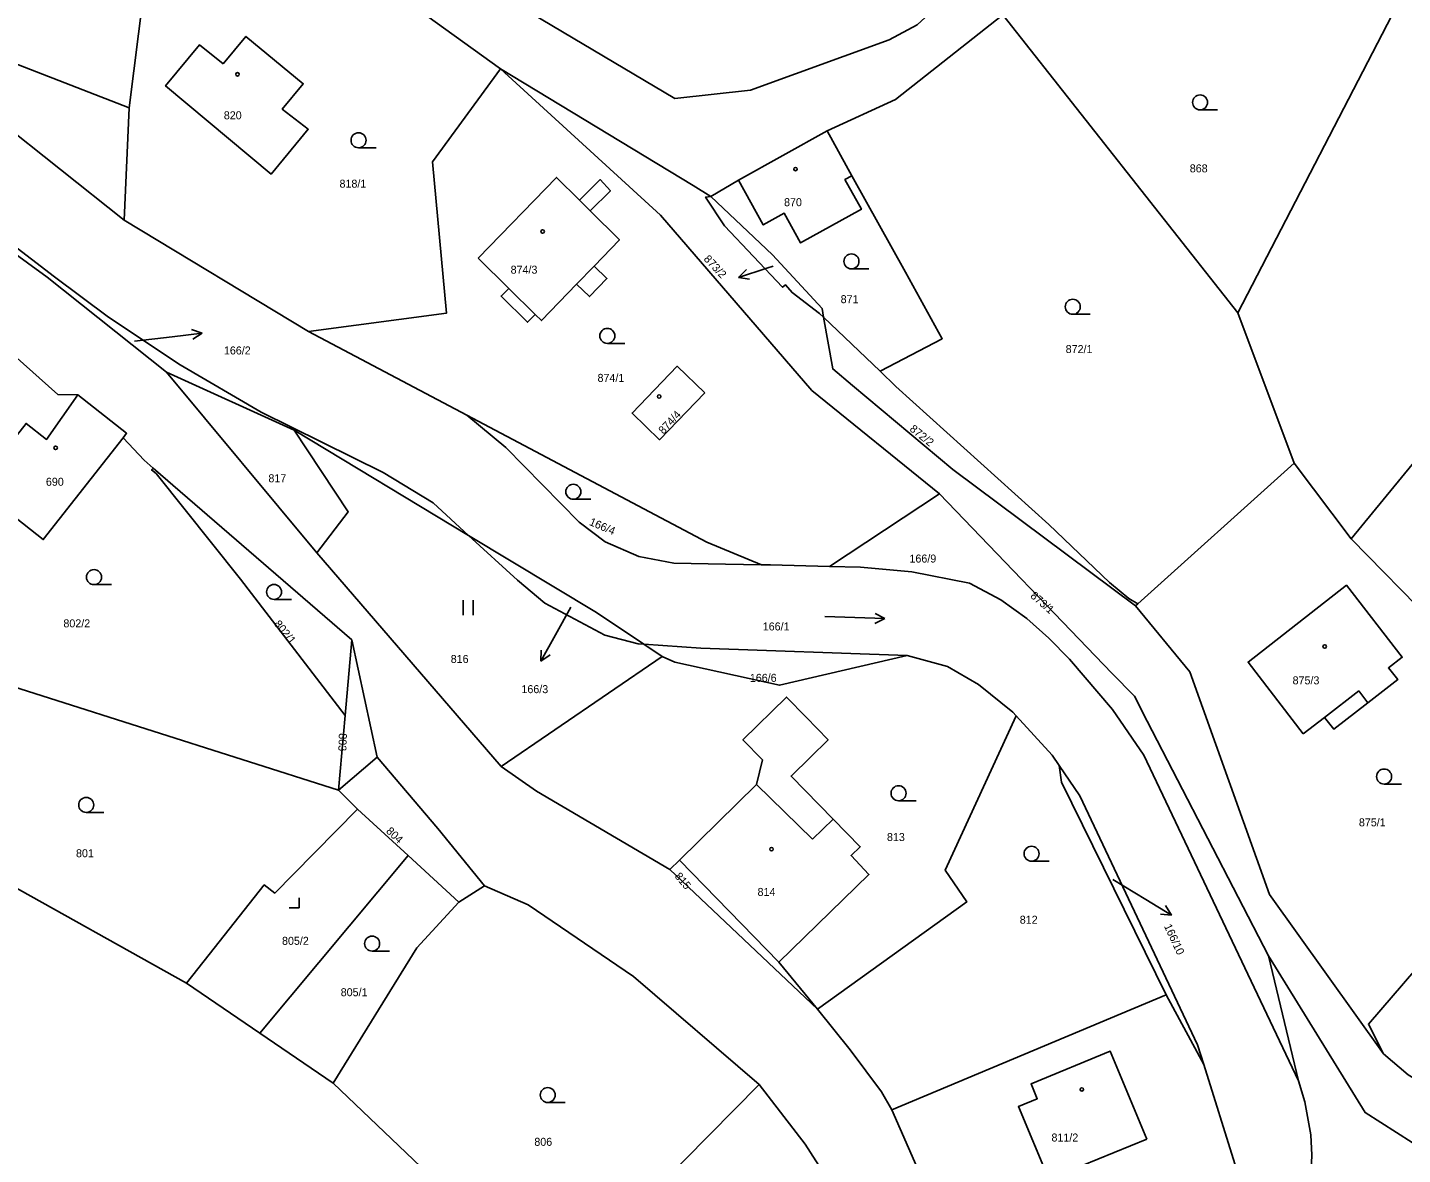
# Model space of a CAD drawing. Extents: x -719706 to -718922, y -950351 to -949651.
# Drawn here: x -719188 to -719050.5, y -949873.5 to -949760.8 of the extents above; entities that cross this region are included whole.
import ezdxf

# ---------------------------------------------------------------- set-up
doc = ezdxf.new("R2010")
doc.units = 0
doc.layers.add('Doplňující texty', color=7, linetype='Continuous')

msp = doc.modelspace()

# ---------------------------------------------------------------- linework, layer by layer
at = {"layer": 'Doplňující texty'}
for p, q in [((-719042.89, -949742.78), (-719066.99, -949789.29)), ((-719175.76, -949752.13), (-719177.82, -949768.78)), ((-719090.47, -949759.49), (-719066.99, -949789.29)), ((-719055.65, -949811.9), (-719019.34, -949767.65)), ((-719191.88, -949769.27), (-719178.32, -949780.03)), ((-719177.82, -949768.78), (-719178.32, -949780.03)), ((-719070.75, -949769), (-719069, -949769)), ((-719116.91, -949776.03), (-719108.05, -949771.11)), ((-719105.57, -949775.59), (-719108.05, -949771.11)), ((-719154.9, -949772.79), (-719153.15, -949772.79)), ((-719119.68, -949777.65), (-719116.91, -949776.03)), ((-719132.8, -949778.04), (-719131.73, -949779.11)), ((-719178.32, -949780.03), (-719159.9, -949791.16)), ((-719133.1, -949786.44), (-719131.35, -949784.63)), ((-719114.06, -949784.83), (-719116.91, -949785.76)), ((-719116.91, -949785.76), (-719116.12, -949784.97)), ((-719116.91, -949785.76), (-719115.81, -949785.92)), ((-719113.45, -949784.63), (-719114.06, -949784.83)), ((-719105.61, -949784.9), (-719103.86, -949784.9)), ((-719139.88, -949786.85), (-719137.24, -949789.46)), ((-719108.39, -949789.74), (-719102.75, -949795.14)), ((-719083.48, -949789.44), (-719081.73, -949789.44)), ((-719066.99, -949789.29), (-719061.35, -949804.33)), ((-719173.52, -949791.69), (-719170.54, -949791.32)), ((-719170.54, -949791.32), (-719171.6, -949790.95)), ((-719170.54, -949791.32), (-719171.47, -949791.94)), ((-719159.9, -949791.16), (-719144.08, -949799.53)), ((-719177.31, -949792.14), (-719173.52, -949791.69)), ((-719130.02, -949792.35), (-719128.27, -949792.35)), ((-719161.33, -949801.03), (-719174.09, -949795.23)), ((-719174.09, -949795.23), (-719159.08, -949813.29)), ((-719143.89, -949811.56), (-719161.33, -949801.03)), ((-719155.58, -949822), (-719175.43, -949804.83)), ((-719061.35, -949804.33), (-719076.99, -949818.41)), ((-719061.35, -949804.33), (-719055.65, -949811.9)), ((-719107.81, -949814.65), (-719096.82, -949807.39)), ((-719133.42, -949807.94), (-719131.67, -949807.94)), ((-719032.5, -949835.55), (-719055.65, -949811.9)), ((-719159.08, -949813.29), (-719140.63, -949834.66)), ((-719181.35, -949816.48), (-719179.6, -949816.48)), ((-719163.35, -949817.96), (-719161.6, -949817.96)), ((-719144.45, -949819.53), (-719144.45, -949818.03)), ((-719143.45, -949819.53), (-719143.45, -949818.03)), ((-719133.67, -949818.74), (-719135.22, -949821.51)), ((-719076.99, -949818.41), (-719077.2, -949818.6)), ((-719108.27, -949819.67), (-719102.28, -949819.88)), ((-719102.28, -949819.88), (-719103.27, -949820.35)), ((-719102.28, -949819.88), (-719103.23, -949819.35)), ((-719135.22, -949821.51), (-719136.68, -949824.14)), ((-719155.58, -949822), (-719156.24, -949829.55)), ((-719153.03, -949833.74), (-719155.58, -949822)), ((-719124.53, -949823.66), (-719126.37, -949822.43)), ((-719124.53, -949823.66), (-719140.63, -949834.66)), ((-719136.68, -949824.14), (-719136.63, -949823.02)), ((-719136.68, -949824.14), (-719135.75, -949823.5)), ((-719058.3, -949829.75), (-719054.89, -949827.1)), ((-719054.89, -949827.1), (-719053.97, -949828.29)), ((-719156.24, -949829.55), (-719156.9, -949837.02)), ((-719156.9, -949837.02), (-719153.03, -949833.74)), ((-719109.49, -949841.94), (-719115.09, -949836.47)), ((-719052.35, -949836.42), (-719050.6, -949836.42)), ((-719155.01, -949838.92), (-719156.9, -949837.02)), ((-719100.9, -949838.09), (-719099.15, -949838.09)), ((-719172.11, -949856.35), (-719202.44, -949839.37)), ((-719182.13, -949839.26), (-719180.38, -949839.26)), ((-719155.01, -949838.92), (-719149.93, -949843.57)), ((-719107.43, -949839.93), (-719109.49, -949841.94)), ((-719149.93, -949843.57), (-719164.78, -949861.33)), ((-719149.93, -949843.57), (-719144.86, -949848.23)), ((-719123.77, -949844.95), (-719122.82, -949844.02)), ((-719123.77, -949844.95), (-719109, -949858.95)), ((-719122.82, -949844.02), (-719112.86, -949854.22)), ((-719087.6, -949844.14), (-719085.85, -949844.14)), ((-719079.47, -949845.98), (-719076.18, -949847.97)), ((-719144.86, -949848.23), (-719142.29, -949846.61)), ((-719161.85, -949848.81), (-719160.85, -949848.81)), ((-719160.85, -949848.81), (-719160.85, -949847.81)), ((-719144.86, -949848.23), (-719149.06, -949852.81)), ((-719076.18, -949847.97), (-719073.61, -949849.52)), ((-719073.61, -949849.52), (-719074.21, -949848.57)), ((-719073.61, -949849.52), (-719074.72, -949849.43)), ((-719149.06, -949852.81), (-719157.45, -949866.32)), ((-719153.54, -949853.13), (-719151.79, -949853.13)), ((-719112.86, -949854.22), (-719109, -949858.95)), ((-719063.9, -949853.6), (-719060.91, -949866.11)), ((-719164.78, -949861.33), (-719172.11, -949856.35)), ((-719074.15, -949857.51), (-719101.57, -949868.99)), ((-719070.39, -949864.47), (-719074.15, -949857.51)), ((-719157.45, -949866.32), (-719164.78, -949861.33)), ((-719147.21, -949876.1), (-719157.45, -949866.32)), ((-719126.51, -949878.29), (-719114.85, -949866.47)), ((-719135.98, -949868.27), (-719134.23, -949868.27))]:
    msp.add_line(p, q, dxfattribs=at)
for points in [[(-719076.41, -949737.98), (-719093.44, -949755.34), (-719099.03, -949760.49), (-719101.84, -949762.01), (-719115.71, -949767.02), (-719123.28, -949767.87), (-719141.64, -949756.93)], [(-719175.76, -949752.13), (-719179.99, -949750.91), (-719190.89, -949748.65), (-719197.5, -949750), (-719196.74, -949746.24), (-719200.64, -949745.44), (-719201.8, -949751.13), (-719201.82, -949751.19), (-719202.67, -949755.38), (-719193.56, -949762.7), (-719177.82, -949768.78)], [(-719174.77, -949747.18), (-719169.6, -949749.95), (-719148.07, -949759.6), (-719140.69, -949764.91)], [(-719108.05, -949771.11), (-719101.21, -949767.96), (-719090.47, -949759.49)], [(-719168.43, -949764.38), (-719166.16, -949761.66), (-719160.42, -949766.39), (-719162.53, -949768.92), (-719159.93, -949770.93), (-719163.65, -949775.42), (-719174.19, -949766.61), (-719170.79, -949762.49), (-719168.43, -949764.38)], [(-719159.9, -949791.16), (-719146.11, -949789.33), (-719147.5, -949774.2), (-719140.69, -949764.91)], [(-719140.69, -949764.91), (-719121.45, -949776.56), (-719119.68, -949777.65)], [(-719096.82, -949807.39), (-719109.57, -949797.06), (-719124.72, -949779.54), (-719140.69, -949764.91)], [(-719208.46, -949767.94), (-719185.3, -949785.71), (-719179.91, -949789.73), (-719172.75, -949794.5), (-719164.64, -949799.24), (-719152.43, -949805.26), (-719147.43, -949808.31), (-719143.89, -949811.56)], [(-719203.76, -949772.83), (-719186.02, -949785.73), (-719174.09, -949795.23)], [(-719142.95, -949783.82), (-719135.1, -949775.75), (-719132.8, -949778.04), (-719130.73, -949775.97), (-719129.71, -949777.08), (-719131.73, -949779.11), (-719128.81, -949782.01), (-719131.35, -949784.63), (-719130.07, -949785.86), (-719131.82, -949787.67), (-719133.1, -949786.44), (-719136.62, -949790.07), (-719137.24, -949789.46), (-719138, -949790.23), (-719140.64, -949787.62), (-719139.88, -949786.85), (-719142.95, -949783.82)], [(-719116.91, -949776.03), (-719114.43, -949780.5), (-719112.33, -949779.34), (-719110.69, -949782.3), (-719104.62, -949778.94), (-719106.26, -949775.97), (-719105.57, -949775.59)], [(-719102.75, -949795.14), (-719096.53, -949791.89), (-719100.22, -949785.24), (-719105.57, -949775.59)], [(-719108.39, -949789.74), (-719108.79, -949789.35), (-719111.54, -949787.27), (-719112.22, -949786.48), (-719112.5, -949786.73), (-719118.32, -949780.59), (-719120.19, -949777.72), (-719119.68, -949777.65)], [(-719119.68, -949777.65), (-719113.5, -949783.5), (-719108.54, -949788.86), (-719108.39, -949789.74)], [(-719108.39, -949789.74), (-719107.48, -949794.9), (-719105.49, -949796.57), (-719095.49, -949804.97), (-719077.2, -949818.6)], [(-719182.96, -949797.5), (-719184.97, -949797.45), (-719189.32, -949793.56)], [(-719120.27, -949797.31), (-719124.81, -949801.99), (-719127.54, -949799.32), (-719123.04, -949794.63), (-719120.27, -949797.31)], [(-719102.75, -949795.14), (-719101.16, -949796.67), (-719085.86, -949810.46), (-719079.8, -949816.26), (-719077.86, -949817.86), (-719076.99, -949818.41)], [(-719182.96, -949797.5), (-719186.09, -949801.96), (-719188.14, -949800.35), (-719193.13, -949806.71), (-719186.42, -949811.97), (-719178.45, -949801.8)], [(-719178.45, -949801.8), (-719178.09, -949801.34), (-719182.96, -949797.5)], [(-719114.6, -949814.49), (-719118.2, -949814.44), (-719123.37, -949814.32), (-719126.87, -949813.65), (-719130.23, -949812.21), (-719132.85, -949810.24), (-719140.16, -949802.75), (-719144.08, -949799.53)], [(-719144.08, -949799.53), (-719120.06, -949812.23), (-719114.6, -949814.49)], [(-719175.43, -949804.83), (-719176.34, -949804.04), (-719178.45, -949801.8)], [(-719161.33, -949801.03), (-719155.92, -949809.19), (-719159.08, -949813.29)], [(-719175.43, -949804.83), (-719175.6, -949805.01), (-719175.15, -949805.35), (-719166.69, -949815.94), (-719156.24, -949829.55)], [(-719063.9, -949853.6), (-719076.03, -949830.13), (-719077.32, -949827.64), (-719079.56, -949825.32), (-719096.82, -949807.39)], [(-719143.89, -949811.56), (-719131.09, -949819.28), (-719126.37, -949822.43)], [(-719126.37, -949822.43), (-719126.93, -949822.4), (-719130.28, -949821.53), (-719136.26, -949818.32), (-719139.01, -949816.03), (-719143.89, -949811.56)], [(-719114.6, -949814.49), (-719113.72, -949814.5), (-719107.81, -949814.65)], [(-719060.91, -949866.11), (-719076.37, -949833.54), (-719079.51, -949828.96), (-719083.82, -949823.92), (-719085.86, -949821.82), (-719088.06, -949819.87), (-719090.67, -949818), (-719093.81, -949816.32), (-719099.57, -949815.2), (-719104.69, -949814.73), (-719107.81, -949814.65)], [(-719060.43, -949831.4), (-719065.95, -949824.23), (-719056.12, -949816.54), (-719050.54, -949823.74), (-719051.91, -949824.81), (-719050.99, -949825.97), (-719053.97, -949828.29), (-719057.37, -949830.94), (-719058.3, -949829.75), (-719060.43, -949831.4)], [(-719077.2, -949818.6), (-719071.76, -949825.19), (-719063.81, -949847.47), (-719052.4, -949863.41)], [(-719156.9, -949837.02), (-719195.46, -949824.78), (-719211.04, -949820.5)], [(-719126.37, -949822.43), (-719120.68, -949822.83), (-719100.05, -949823.56)], [(-719100.05, -949823.56), (-719112.8, -949826.54), (-719123.27, -949824.23), (-719124.53, -949823.66)], [(-719089.13, -949829.61), (-719089.49, -949829.22), (-719092.92, -949826.48), (-719096.02, -949824.65), (-719100.05, -949823.56)], [(-719122.82, -949844.02), (-719115.09, -949836.47), (-719114.52, -949833.99), (-719116.47, -949831.99), (-719112.11, -949827.72), (-719110.15, -949829.72), (-719107.94, -949831.99), (-719109.72, -949833.73), (-719111.65, -949835.62), (-719107.43, -949839.93), (-719104.73, -949842.69), (-719105.64, -949843.58), (-719103.86, -949845.48), (-719112.86, -949854.22)], [(-719089.13, -949829.61), (-719096.25, -949845.04), (-719094.09, -949848.21), (-719109, -949858.95)], [(-719084.83, -949834.57), (-719085.53, -949833.52), (-719089.13, -949829.61)], [(-719142.29, -949846.61), (-719146.97, -949840.86), (-719153.03, -949833.74)], [(-719140.63, -949834.66), (-719137.12, -949837.14), (-719123.77, -949844.95)], [(-719074.15, -949857.51), (-719084.62, -949836.23), (-719084.83, -949834.57)], [(-719084.83, -949834.57), (-719082.78, -949837.61), (-719071.01, -949862.49), (-719070.39, -949864.47)], [(-719052.4, -949863.41), (-719053.91, -949860.42), (-719032.5, -949835.55)], [(-719172.11, -949856.35), (-719169.84, -949853.48), (-719164.32, -949846.5), (-719163.27, -949847.33), (-719161.41, -949845.44), (-719155.01, -949838.92)], [(-719114.85, -949866.47), (-719127.42, -949855.68), (-719137.94, -949848.51), (-719142.29, -949846.61)], [(-719033.87, -949882.27), (-719054.24, -949869.28), (-719063.9, -949853.6)], [(-719109, -949858.95), (-719105.75, -949862.99), (-719102.6, -949867.2), (-719101.57, -949868.99)], [(-719076.08, -949871.93), (-719085.89, -949875.95), (-719088.91, -949868.68), (-719087.03, -949867.9), (-719087.65, -949866.4), (-719079.74, -949863.14), (-719076.08, -949871.93)], [(-719052.4, -949863.41), (-719049.95, -949865.5), (-719044.43, -949868.81), (-719036.15, -949872.35)], [(-719067.94, -949878.61), (-719067.29, -949874.4), (-719070.39, -949864.47)], [(-719100.96, -949898.33), (-719102.01, -949891.27), (-719104.01, -949882.17), (-719110.25, -949872.44), (-719114.85, -949866.47)], [(-719060.91, -949866.11), (-719060.26, -949868.21), (-719059.66, -949871.49), (-719059.57, -949873.53), (-719059.71, -949876.58), (-719061.19, -949883.61), (-719061.93, -949886.22), (-719062.78, -949888.55), (-719063.94, -949890.99), (-719065.34, -949893.32), (-719069.95, -949899.51), (-719072.25, -949902.55), (-719073.6, -949904.5), (-719074.92, -949906.95), (-719075.6, -949908.76), (-719075.7, -949910.05)], [(-719101.57, -949868.99), (-719098.24, -949876.59), (-719094.8, -949888.6), (-719087.19, -949907.49)]]:
    msp.add_lwpolyline(points, dxfattribs=at)
for centre, radius in [((-719167, -949765.44), 0.175), ((-719070.75, -949768.25), 0.75), ((-719154.9, -949772.04), 0.75), ((-719111.2, -949774.92), 0.175), ((-719136.49, -949781.16), 0.175), ((-719105.61, -949784.15), 0.75), ((-719083.48, -949788.69), 0.75), ((-719130.02, -949791.6), 0.75), ((-719124.84, -949797.66), 0.175), ((-719185.19, -949802.79), 0.175), ((-719133.42, -949807.19), 0.75), ((-719181.35, -949815.73), 0.75), ((-719163.35, -949817.21), 0.75), ((-719058.29, -949822.67), 0.175), ((-719052.35, -949835.67), 0.75), ((-719100.9, -949837.34), 0.75), ((-719182.13, -949838.51), 0.75), ((-719113.61, -949842.93), 0.175), ((-719087.6, -949843.39), 0.75), ((-719153.54, -949852.38), 0.75), ((-719135.98, -949867.52), 0.75), ((-719082.58, -949866.96), 0.175)]:
    msp.add_circle(centre, radius, dxfattribs=at)

# ---------------------------------------------------------------- texts
for s, p in [('820', (-719168.37, -949769.94)), ('868', (-719071.78, -949775.25)), ('818/1', (-719156.8, -949776.78)), ('870', (-719112.35, -949778.63)), ('874/3', (-719139.69, -949785.38)), ('871', (-719106.69, -949788.33)), ('166/2', (-719168.36, -949793.46)), ('872/1', (-719084.19, -949793.32)), ('874/1', (-719131, -949796.2)), ('690', (-719186.16, -949806.59)), ('817', (-719163.91, -949806.24)), ('166/9', (-719099.81, -949814.27)), ('802/2', (-719184.41, -949820.75)), ('166/1', (-719114.48, -949821.06)), ('816', (-719145.68, -949824.31)), ('166/6', (-719115.77, -949826.2)), ('875/3', (-719061.5, -949826.45)), ('166/3', (-719138.61, -949827.33)), ('875/1', (-719054.87, -949840.65)), ('813', (-719102.06, -949842.12)), ('801', (-719183.15, -949843.74)), ('814', (-719115, -949847.61)), ('812', (-719088.78, -949850.39)), ('805/2', (-719162.55, -949852.5)), ('805/1', (-719156.68, -949857.64)), ('806', (-719137.32, -949872.6)), ('811/2', (-719085.61, -949872.17))]:
    msp.add_text(s, height=0.8, dxfattribs=at).set_placement(p)
for s, rotation, p in [('873/2', 313, (-719120.44, -949783.96)), ('874/4', 47, (-719124.41, -949801.49)), ('872/2', 321, (-719099.86, -949801.03)), ('166/4', 337, (-719131.9, -949810.49)), ('873/1', 319, (-719087.79, -949817.7)), ('802/1', 309, (-719163.4, -949820.43)), ('803', 268, (-719156.86, -949831.33)), ('804', 317, (-719152.21, -949841.21)), ('815', 310, (-719123.34, -949845.67)), ('166/10', 295, (-719074.38, -949850.63))]:
    msp.add_text(s, height=0.8, rotation=rotation, dxfattribs=at).set_placement(p)

doc.saveas('drawing.dxf')
